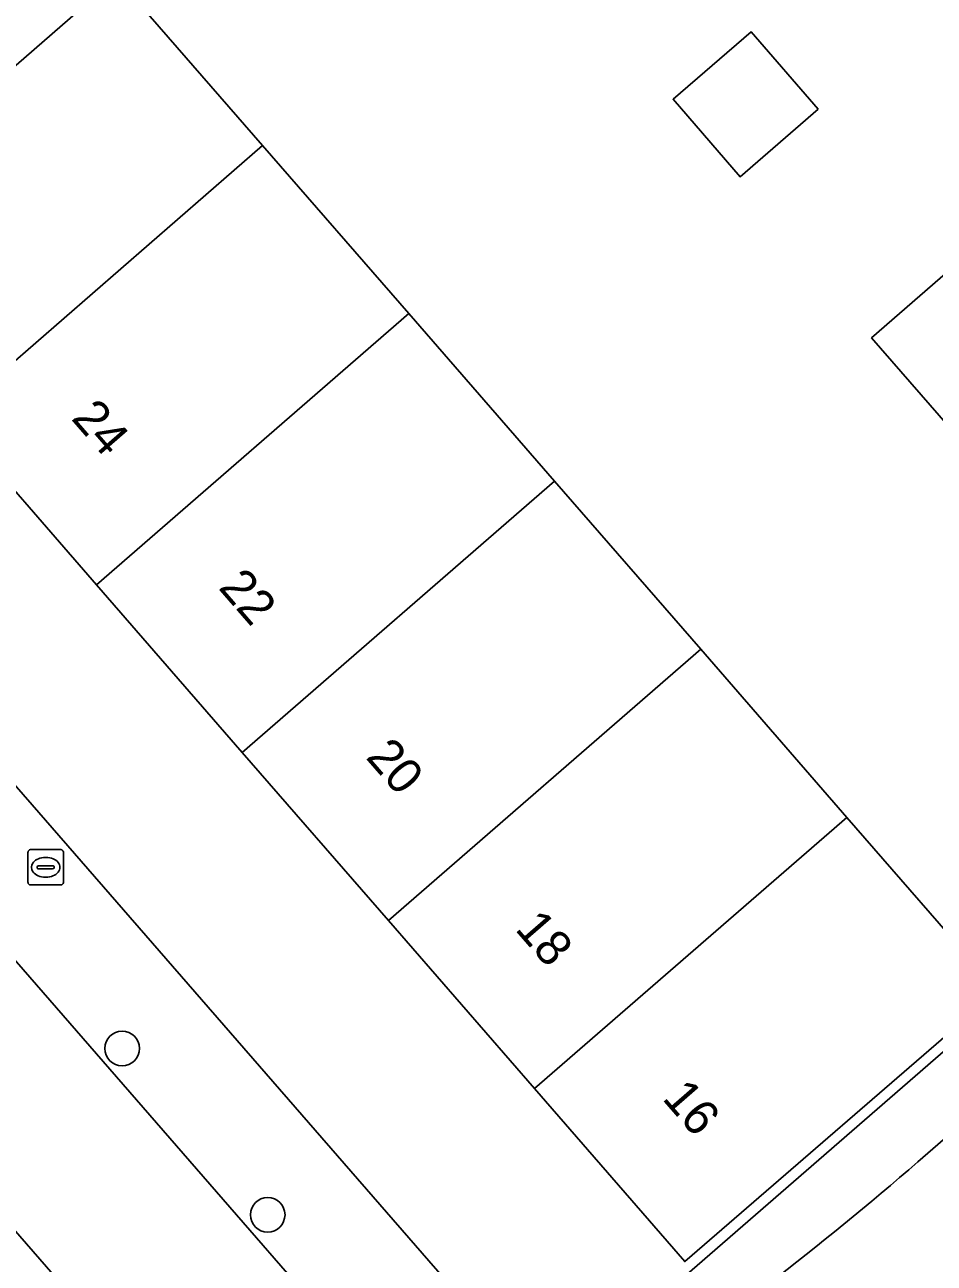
# Model space of a CAD drawing. Extents: x 155887 to 156869, y 383880 to 384678.
# Drawn here: x 156346.67 to 156372.39, y 384014.44 to 384049.47 of the extents above; entities that cross this region are included whole.
import ezdxf

# ---------------------------------------------------------------- set-up
doc = ezdxf.new("R2010")
doc.units = 0
for name, color, linetype in [('IMGEO_Boom', 7, 'Continuous'), ('IMGEO_Brandkraan', 7, 'Continuous'), ('IMGEO_Erf', 7, 'Continuous'), ('IMGEO_Pand', 7, 'Continuous'), ('IMGEO_Pand_nummerreeks', 7, 'Continuous'), ('IMGEO_Rijbaan_lokaal_gesloten', 7, 'Continuous'), ('IMGEO_Rijbaan_lokaal_open', 7, 'Continuous'), ('IMGEO_Voetpad_open', 7, 'Continuous')]:
    doc.layers.add(name, color=color, linetype=linetype)

msp = doc.modelspace()

# ---------------------------------------------------------------- linework, layer by layer
at = {"layer": 'IMGEO_Boom'}
for centre in [(156349.426, 384020.515), (156353.543, 384015.81)]:
    msp.add_circle(centre, 0.489, dxfattribs=at)
at = {"layer": 'IMGEO_Brandkraan'}
for p, q in [((156346.838, 384026.14), (156347.69, 384026.14)), ((156346.763, 384025.214), (156346.763, 384026.066)), ((156347.251, 384025.92), (156347.276, 384025.92)), ((156347.764, 384026.066), (156347.764, 384025.214)), ((156347.022, 384025.634), (156347.022, 384025.646)), ((156347.46, 384025.597), (156347.062, 384025.597)), ((156347.065, 384025.683), (156347.463, 384025.683)), ((156347.506, 384025.646), (156347.506, 384025.634)), ((156347.69, 384025.14), (156346.838, 384025.14)), ((156347.274, 384025.36), (156347.249, 384025.36))]:
    msp.add_line(p, q, dxfattribs=at)
for points in [[(156346.838, 384026.14), (156347.69, 384026.14)], [(156346.763, 384025.214), (156346.763, 384026.066)], [(156347.764, 384026.066), (156347.764, 384025.214)], [(156347.69, 384025.14), (156346.838, 384025.14)]]:
    msp.add_lwpolyline(points, dxfattribs=at)
for centre, radius, start, end in [((156346.84, 384026.064), 0.0765, 91.552, 178.448), ((156346.84, 384026.064), 0.0765, 91.552, 178.448), ((156347.688, 384026.064), 0.0765, 1.552, 88.448), ((156347.688, 384026.064), 0.0765, 1.552, 88.448), ((156347.062, 384025.643), 0.0403, 85.8775, 175.7526), ((156347.059, 384025.633), 0.0366, 178.938, 274.7102), ((156347.463, 384025.64), 0.043, 264.8664, 352.4533), ((156347.467, 384025.645), 0.0386, 1.7309, 96.639), ((156346.84, 384025.216), 0.0765, 181.552, 268.448), ((156346.84, 384025.216), 0.0765, 181.552, 268.448), ((156347.688, 384025.216), 0.0765, 271.552, 358.448), ((156347.688, 384025.216), 0.0765, 271.552, 358.448)]:
    msp.add_arc(centre, radius, start, end, dxfattribs=at)
for centre, major_axis, ratio, start_param, end_param in [((156347.25, 384025.64), (-0.387, 0.002), 0.722429, 4.712389, 7.853982), ((156347.275, 384025.64), (-0.39, 0.002), 0.717154, 1.570796, 4.712389)]:
    msp.add_ellipse(centre, major_axis=major_axis, ratio=ratio, start_param=start_param, end_param=end_param, dxfattribs=at)
at = {"layer": 'IMGEO_Erf'}
for points in [[(156372.634, 384088.199), (156329.142, 384050.413), (156328.149, 384048.934), (156360.938, 384011.241), (156362.61, 384011.694), (156406.195, 384049.568)], [(156374.189, 384022.144), (156365.338, 384014.487), (156361.085, 384019.381), (156356.957, 384024.132), (156352.823, 384028.89), (156348.703, 384033.632), (156344.574, 384038.383), (156340.448, 384043.132), (156336.32, 384047.883), (156332.03, 384052.82), (156340.861, 384060.488), (156342.001, 384061.483), (156347.913, 384066.639), (156348.044, 384066.488), (156342.126, 384061.327), (156340.992, 384060.338), (156345.147, 384055.557), (156349.27, 384050.813), (156353.399, 384046.062), (156357.534, 384041.306), (156361.657, 384036.563), (156365.79, 384031.808), (156369.924, 384027.051), (156374.058, 384022.295)], [(156373.109, 384037.757), (156370.621, 384040.614), (156376.879, 384046.055)]]:
    msp.add_lwpolyline(points, dxfattribs=at)
msp.add_lwpolyline([(156369.112, 384047.082), (156366.905, 384045.172), (156365.006, 384047.365), (156367.212, 384049.276)], close=True, dxfattribs=at)
at = {"layer": 'IMGEO_Pand'}
for points in [[(156340.448, 384043.132), (156349.27, 384050.813), (156345.147, 384055.557), (156336.32, 384047.883)], [(156340.448, 384043.132), (156344.574, 384038.383), (156353.399, 384046.062), (156349.27, 384050.813)], [(156369.112, 384047.082), (156367.212, 384049.276), (156365.006, 384047.365), (156366.905, 384045.172)], [(156353.399, 384046.062), (156344.574, 384038.383), (156348.703, 384033.632), (156357.534, 384041.306)], [(156376.879, 384046.055), (156370.621, 384040.614), (156373.109, 384037.757), (156376.72, 384040.895), (156379.802, 384037.349), (156376.188, 384034.208), (156379.238, 384030.7), (156382.093, 384033.169), (156383.771, 384031.228), (156387.188, 384034.199)], [(156361.657, 384036.563), (156357.534, 384041.306), (156348.703, 384033.632), (156352.823, 384028.89)], [(156356.957, 384024.132), (156365.79, 384031.808), (156361.657, 384036.563), (156352.823, 384028.89)], [(156369.924, 384027.051), (156365.79, 384031.808), (156356.957, 384024.132), (156361.085, 384019.381)], [(156369.924, 384027.051), (156361.085, 384019.381), (156365.338, 384014.487), (156374.189, 384022.144), (156374.058, 384022.295)]]:
    msp.add_lwpolyline(points, close=True, dxfattribs=at)
at = {"layer": 'IMGEO_Rijbaan_lokaal_gesloten'}
for points in [[(156317.543, 384056.292), (156284.205, 384094.584), (156280.427, 384091.296), (156283.957, 384087.246), (156289.413, 384080.986), (156306.544, 384061.236), (156310.724, 384056.416), (156314.044, 384052.599), (156341.332, 384021.196), (156345.148, 384016.792), (156359.753, 384000), (156367.328, 383991.29), (156368.7, 383989.651), (156369.329, 383988.906)], [(156449.055, 384084.789), (156448.166, 384083.918), (156444.013, 384079.846), (156371.934, 384017.308)], [(156357.31, 384010.459), (156327.395, 384044.864)]]:
    msp.add_lwpolyline(points, dxfattribs=at)
msp.add_arc((156310.186, 384088.593), 94.31, 304.25053, 310.89943, dxfattribs=at)
at = {"layer": 'IMGEO_Rijbaan_lokaal_open'}
msp.add_lwpolyline([(156369.329, 383988.906), (156368.7, 383989.651), (156367.328, 383991.29), (156359.753, 384000), (156345.148, 384016.792), (156341.332, 384021.196), (156314.044, 384052.599), (156310.724, 384056.416), (156306.544, 384061.236), (156289.413, 384080.986), (156283.957, 384087.246), (156280.427, 384091.296)], dxfattribs=at)
at = {"layer": 'IMGEO_Voetpad_open'}
for points in [[(156444.013, 384079.846), (156448.166, 384083.918), (156447.142, 384085.078), (156410.122, 384052.983), (156407.826, 384050.978), (156406.195, 384049.568), (156362.61, 384011.694), (156360.938, 384011.241), (156362.105, 384009.899), (156362.712, 384010.226), (156363.265, 384010.638)], [(156371.934, 384017.308), (156444.013, 384079.846)], [(156362.105, 384009.899), (156360.938, 384011.241), (156328.149, 384048.934)], [(156327.395, 384044.864), (156357.31, 384010.459)]]:
    msp.add_lwpolyline(points, dxfattribs=at)
msp.add_arc((156310.186, 384088.593), 94.31, 304.25053, 310.89943, dxfattribs=at)

# ---------------------------------------------------------------- texts
at = {"layer": 'IMGEO_Pand_nummerreeks'}
for s, p in [('24', (156347.963, 384038.326)), ('22', (156352.125, 384033.537)), ('20', (156356.292, 384028.741)), ('18', (156360.515, 384023.881)), ('16', (156364.676, 384019.091))]:
    msp.add_text(s, height=1, rotation=310.9878, dxfattribs=at).set_placement(p)

doc.saveas('drawing.dxf')
